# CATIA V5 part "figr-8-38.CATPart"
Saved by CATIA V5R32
Part number: Part2
Bounding box of the stored display mesh (mm): x -50 to 50, y -50 to 50, z 0 to 40
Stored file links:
  D:\PROJECTS\Project 2022\CATIA V5 6R 2022\Resources\Part Files\c08_catia_v5_6r2022_prt\figr-8-38.CATPart
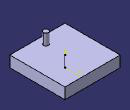
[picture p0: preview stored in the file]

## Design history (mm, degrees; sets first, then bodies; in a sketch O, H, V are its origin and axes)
Body1 (main body)
  Sketch1 on xy-plane, origin (0, 0, 0), H (1, 0, 0), V (0, 1, 0)
    line L1 (-50, 50) -> (50, 50)
    line L2 (50, 50) -> (50, -50)
    line L3 (50, -50) -> (-50, -50)
    line L4 (-50, -50) -> (-50, 50)
    axis line L5 (50, -50) -> (-50, 50)
    length L2 = 100
    length L3 = 100
    horizontal: L1 H, L3 H
    vertical: L2 V, L4 V
    midpoint: O L5
  Pad1: profile Sketch1, direction (0, 0, 1), length 20
  Sketch2 on face of Pad1, origin (0, 0, 20), H (1, 0, 0), V (0, 1, 0)
    circle A1 centre (0, -34.6458) radius 4.7511
    point P1 (0, -34.6458)
    coincidence: P1 V
  Pad2: profile Sketch2, direction (0, 0, 1), length 20
  Sketch3 on yz-plane, origin (0, 0, 0), H (0, 1, 0), V (0, 0, 1)
    line L1 (0, 0) -> (0, 20.0386)
    vertical: L1 V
